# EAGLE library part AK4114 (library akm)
Digital Audio Transmitter (DIT) 8:1 Selector, 24-Bit, 192 kHz
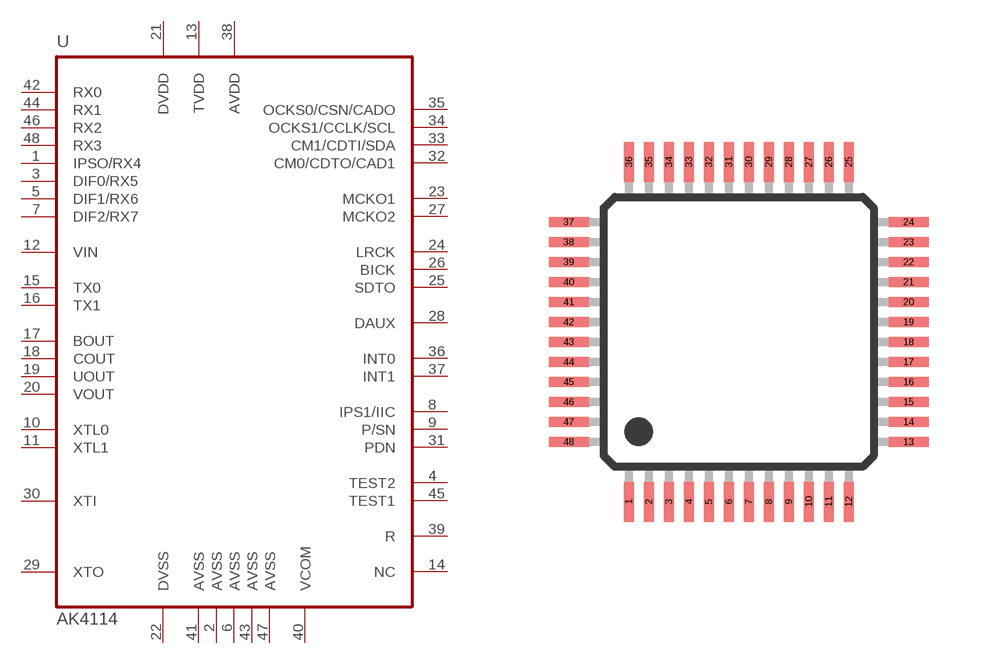
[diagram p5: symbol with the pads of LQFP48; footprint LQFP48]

Designator prefix U

## AK4114  [LQFP48]
1  IPSO/RX4  in
2  AVSS1  pwr
3  DIF0/RX5  in
4  TEST2  in
5  DIF1/RX6  in
6  AVSS2  pwr
7  DIF2/RX7  in
8  IPS1/IIC  in
9  P/SN  in
10  XTL0  in
11  XTL1  in
12  VIN  in
13  TVDD  pwr
14  NC  in
15  TX0  out
16  TX1  out
17  BOUT  out
18  COUT  out
19  UOUT  out
20  VOUT  out
21  DVDD  pwr
22  DVSS  pwr
23  MCKO1  out
24  LRCK
25  SDTO  out
26  BICK
27  MCKO2  out
28  DAUX  in
29  XTO  out
30  XTI  in
31  PDN  in
32  CM0/CDTO/CAD1
33  CM1/CDTI/SDA
34  OCKS1/CCLK/SCL  in
35  OCKS0/CSN/CADO  in
36  INT0  out
37  INT1  out
38  AVDD  pwr
39  R  pas
40  VCOM  pas
41  AVSS  pwr
42  RX0  in
43  AVSS3  pwr
44  RX1  in
45  TEST1  in
46  RX2  in
47  AVSS4  pwr
48  RX3  in

## Footprint LQFP48 (pad centres in mm)
LQFP48
smd 0.25 x 1: 1 -2.75,-4.25; 2 -2.25,-4.25; 3 -1.75,-4.25; 4 -1.25,-4.25; 5 -0.75,-4.25; 6 -0.25,-4.25; 7 0.25,-4.25; 8 0.75,-4.25; 9 1.25,-4.25; 10 1.75,-4.25; 11 2.25,-4.25; 12 2.75,-4.25; 25 2.75,4.25; 26 2.25,4.25; 27 1.75,4.25; 28 1.25,4.25; 29 0.75,4.25; 30 0.25,4.25; 31 -0.25,4.25; 32 -0.75,4.25; 33 -1.25,4.25; 34 -1.75,4.25; 35 -2.25,4.25; 36 -2.75,4.25
smd 1 x 0.25: 13 4.25,-2.75; 14 4.25,-2.25; 15 4.25,-1.75; 16 4.25,-1.25; 17 4.25,-0.75; 18 4.25,-0.25; 19 4.25,0.25; 20 4.25,0.75; 21 4.25,1.25; 22 4.25,1.75; 23 4.25,2.25; 24 4.25,2.75; 37 -4.25,2.75; 38 -4.25,2.25; 39 -4.25,1.75; 40 -4.25,1.25; 41 -4.25,0.75; 42 -4.25,0.25; 43 -4.25,-0.25; 44 -4.25,-0.75; 45 -4.25,-1.25; 46 -4.25,-1.75; 47 -4.25,-2.25; 48 -4.25,-2.75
